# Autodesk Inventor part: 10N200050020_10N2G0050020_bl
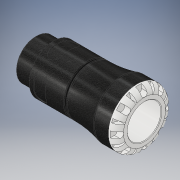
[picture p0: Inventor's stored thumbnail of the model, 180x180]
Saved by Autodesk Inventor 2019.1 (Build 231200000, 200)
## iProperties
Created: 2016-12
Part Number: 10N200050020_10N2G0050020_bl
Material: PVC-Piping
Description: PLASSON MALE ADAPTOR 50X2" SERIES 1
Document SubType Name: Modeling
Designer: KIM
Mass: 61.7504 g
Surface Area: 140.097 cm^2
Volume: 44.1074 cm^3
Density: 1.4 g/cm^3
Appearance: Black Cast
Author: KIM
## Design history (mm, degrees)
derived "10N20.ipt"
feature "Solid1::10N20.ipt" dims "ScaleForDerivedMember" = 10
tag "TaggingFeature1"
body "Solid1"
other parameters: "d0" = 162 [user parameter], "d1" = 32.76 [user parameter], "d3" = 62.5 [user parameter], "d4" = 85 [user parameter], "d6" = 78 [user parameter], "d8" = 72.25 [user parameter], "d13" = 9 [user parameter], "d14" = 9 [user parameter], "d15" = 0 [user parameter], "d17" = 360 deg [user parameter], "d19" = 8 deg [user parameter], "d20" = 1 [user parameter], "d21" = 1 [user parameter], "d22" = 8 deg [user parameter], "d24" = 0 [user parameter], "d26" = 360 deg [user parameter], "d32" = 0.925 [user parameter], "d33" = 8.5 [user parameter], "d34" = 59.614 [user parameter], "d35" = 6.25 [user parameter], "d38" = 26 [user parameter], "d39" = 1.78842 [user parameter], "d42" = 17.5 [user parameter], "d43" = 11.5 [user parameter], "d45" = 17.64 [user parameter], "d46" = 0 [user parameter], "d59" = 360 deg [user parameter], "d61" = 14.875 [user parameter], "d62" = 1 [user parameter], "d64" = 0 [user parameter], "d65" = 0.85 [user parameter], "d69" = 2 [user parameter], "d70" = 2.43 [user parameter], "d71" = 3 [user parameter], "d73" = 1 [user parameter], "E_" = 85 [user parameter], "H_" = 162 [user parameter], "l_" = 78 [user parameter], "R_" = 59.614 [user parameter], "l_2" = 26 [user parameter], "d9" = 11.25 [user parameter], "d11" = 85 [user parameter], "d12" = 62.5 [user parameter]
